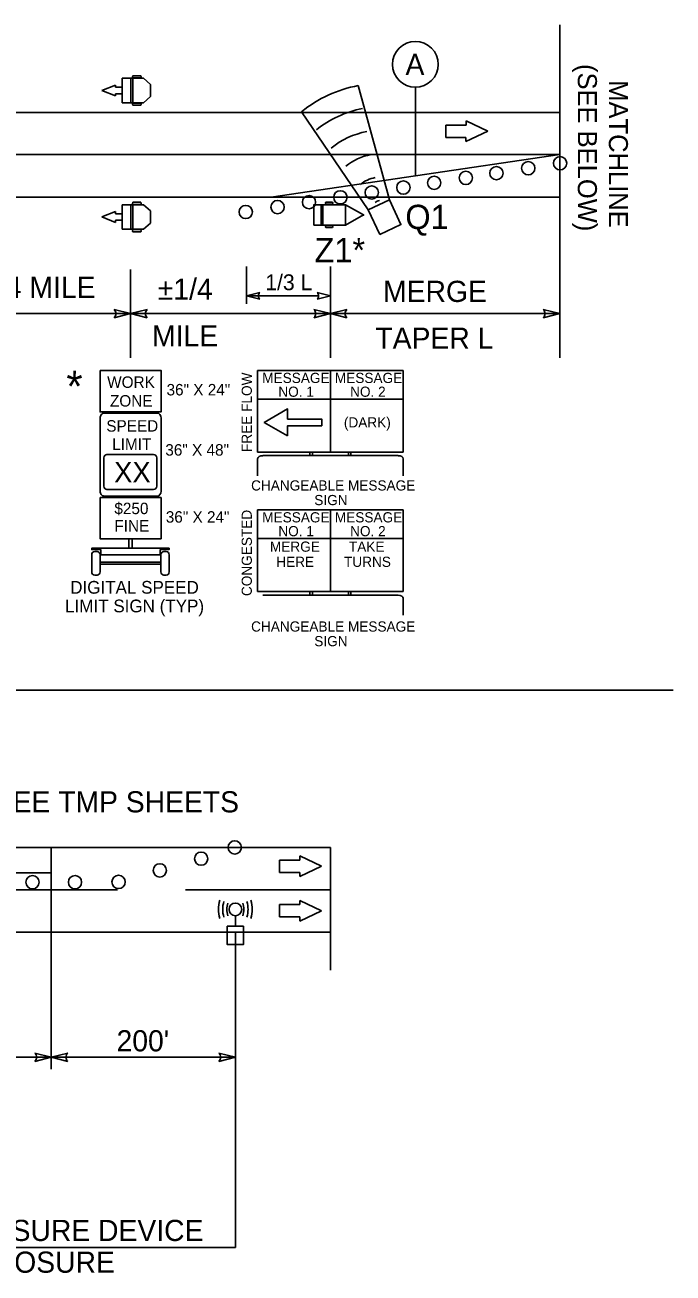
# Model space of a CAD drawing. Extents: x 1379436 to 1387057, y 792703 to 795604.
# Drawn here: x 1386649 to 1387057, y 794807 to 795592 of the extents above; entities that cross this region are included whole.
import ezdxf

# ---------------------------------------------------------------- set-up
doc = ezdxf.new("R2010")
doc.units = 0
for name, color, linetype in [('Black Area Fill Shapes', 7, 'Continuous'), ('Default', 7, 'Continuous'), ('DEV DIRECTION OF TRAFFIC FLOW ARROW CELL', 7, 'Continuous'), ('Gray Area Fill Shapes', 7, 'Continuous'), ('Old_Level_2', 7, 'Continuous'), ('Prop Mkg Skp Wht', 7, 'Continuous'), ('Prop Mkg Solid White Lane Line', 7, 'Continuous'), ('Prop Mkg Solid Yellow Edge Line', 7, 'Continuous'), ('Scratch_Level_0', 7, 'Continuous'), ('Text', 7, 'Continuous')]:
    doc.layers.add(name, color=color, linetype=linetype)

msp = doc.modelspace()

# ---------------------------------------------------------------- linework, layer by layer
at = {"layer": 'Black Area Fill Shapes'}
for points in [[(1386872.29, 795459.93), (1386865.13, 795475.48), (1386878.44, 795481.61), (1386885.6, 795466.07)], [(1386814.38, 795333.26), (1386799.7, 795341.73), (1386814.38, 795350.21), (1386814.38, 795343.86), (1386835.89, 795343.86), (1386835.89, 795339.6), (1386814.38, 795339.6)], [(1386714.52, 795262.58), (1386716.65, 795262.58), (1386716.65, 795268.56), (1386714.52, 795268.56)], [(1386696.46, 795252.5), (1386734.71, 795252.5), (1386734.71, 795253.77), (1386696.46, 795253.77)]]:
    msp.add_lwpolyline(points, close=True, dxfattribs=at)
for points in [[(1386734.7, 795262.58), (1386696.47, 795262.58), (1386691.29, 795262.57), (1386691.29, 795261.74), (1386696.85, 795261.74), (1386696.85, 795258.48), (1386734.3, 795258.51), (1386734.3, 795261.74)], [(1386696.47, 795262.58), (1386734.7, 795262.58), (1386739.88, 795262.57), (1386739.88, 795261.74), (1386734.3, 795261.75), (1386734.29, 795258.46), (1386696.85, 795258.48), (1386696.85, 795261.74)], [(1386691.21, 795247.81), (1386691.21, 795258.46)], [(1386693.12, 795260.54), (1386694.55, 795260.54)], [(1386696.46, 795258.46), (1386696.46, 795247.81)], [(1386734.71, 795247.81), (1386734.71, 795258.46)], [(1386736.62, 795260.54), (1386738.05, 795260.54)], [(1386739.96, 795258.46), (1386739.96, 795247.81)], [(1386694.55, 795245.74), (1386693.12, 795245.74)], [(1386738.05, 795245.74), (1386736.62, 795245.74)]]:
    msp.add_lwpolyline(points, dxfattribs=at)
for centre in [(1386985.71, 795504.66), (1386926.49, 795495.49), (1386945.7, 795498.46), (1386965.73, 795501.56), (1386867.28, 795486.31), (1386887.19, 795489.4), (1386906.57, 795492.4), (1386827.86, 795480.21), (1386847.57, 795483.26), (1386788.06, 795474.04), (1386808.08, 795477.14), (1386781.14, 795074.47), (1386760.03, 795067.39), (1386734.07, 795060.04), (1386653.98, 795052.57), (1386680.72, 795052.58), (1386708.13, 795052.74)]:
    msp.add_circle(centre, 4.18, dxfattribs=at)
for centre, major_axis, start_param, end_param in [((1386693.12, 795258.46), (0, 2.08), 0, 1.570796), ((1386694.55, 795258.46), (0, 2.08), 4.712389, 6.283185), ((1386736.62, 795258.46), (0, -2.08), 3.141593, 4.712389), ((1386738.05, 795258.46), (0, 2.08), 4.712389, 6.283185), ((1386693.12, 795247.81), (0, -2.08), 4.712389, 6.283185), ((1386694.55, 795247.81), (0, -2.08), 0, 1.570796), ((1386736.62, 795247.81), (0, -2.08), 4.712389, 6.283185), ((1386738.05, 795247.81), (0, 2.08), 3.141593, 4.712389)]:
    msp.add_ellipse(centre, major_axis=major_axis, ratio=0.917264, start_param=start_param, end_param=end_param, dxfattribs=at)
at = {"layer": 'Default'}
for p, q in [((1386985.54, 795428.56), (1386985.54, 795591.65)), ((1386894.75, 795496.78), (1386894.75, 795552.5)), ((1386715.67, 795437.87), (1386715.67, 795382.35)), ((1386788.53, 795439.68), (1386788.53, 795416.27)), ((1386841.32, 795439.68), (1386841.32, 795382.35)), ((1386985.54, 795439.68), (1386985.54, 795382.35)), ((1386788.53, 795421.29), (1386833.85, 795421.29)), ((1386985.54, 795410.11), (1385695.67, 795410.11)), ((1384806.76, 795173.42), (1387056.77, 795173.42))]:
    msp.add_line(p, q, dxfattribs=at)
for points in [[(1386696.55, 795298.44), (1386696.55, 795344.47)], [(1386698.78, 795347.51), (1386732.56, 795347.51)], [(1386734.79, 795344.47), (1386734.79, 795298.44)], [(1386732.56, 795295.4), (1386698.78, 795295.4)]]:
    msp.add_lwpolyline(points, dxfattribs=at)
msp.add_circle((1386894.75, 795566.87), 14.37, dxfattribs=at)
for centre, major_axis, start_param, end_param in [((1386698.78, 795344.47), (0, 3.04), 6.282958, 7.853982), ((1386732.56, 795344.47), (0, 3.04), 4.712389, 6.283185), ((1386698.78, 795298.44), (0, 3.04), 1.570796, 3.141593), ((1386732.56, 795298.44), (0, -3.04), 0, 1.570796)]:
    msp.add_ellipse(centre, major_axis=major_axis, ratio=0.733811, start_param=start_param, end_param=end_param, dxfattribs=at)
at = {"layer": 'DEV DIRECTION OF TRAFFIC FLOW ARROW CELL'}
for p, q in [((1386940.34, 795524.82), (1386926.58, 795531.31)), ((1386926.58, 795531.31), (1386926.58, 795528.69)), ((1386926.58, 795528.69), (1386913.8, 795528.7)), ((1386913.8, 795528.7), (1386913.8, 795520.98)), ((1386926.57, 795518.35), (1386940.34, 795524.82)), ((1386913.8, 795520.98), (1386926.57, 795520.98)), ((1386926.57, 795520.98), (1386926.57, 795518.35)), ((1386822.01, 795066.46), (1386809.24, 795066.47)), ((1386809.24, 795066.47), (1386809.24, 795058.76)), ((1386822.02, 795069.08), (1386822.01, 795066.46)), ((1386835.77, 795062.59), (1386822.02, 795069.08)), ((1386809.24, 795058.76), (1386822.01, 795058.75)), ((1386822.01, 795056.13), (1386835.77, 795062.59)), ((1386822.01, 795058.75), (1386822.01, 795056.13)), ((1386822.01, 795038.52), (1386809.24, 795038.53)), ((1386809.24, 795038.53), (1386809.24, 795030.82)), ((1386822.02, 795041.14), (1386822.01, 795038.52)), ((1386835.77, 795034.66), (1386822.02, 795041.14)), ((1386809.24, 795030.82), (1386822.01, 795030.81)), ((1386822.01, 795028.19), (1386835.77, 795034.66)), ((1386822.01, 795030.81), (1386822.01, 795028.19))]:
    msp.add_line(p, q, dxfattribs=at)
at = {"layer": 'Gray Area Fill Shapes'}
for p, q in [((1386698.81, 795319.44), (1386698.81, 795301.68)), ((1386730.09, 795321.6), (1386700.79, 795321.6)), ((1386732.07, 795301.68), (1386732.07, 795319.44)), ((1386700.79, 795299.52), (1386730.09, 795299.52))]:
    msp.add_line(p, q, dxfattribs=at)
msp.add_lwpolyline([(1386573.89, 795074.47), (1386665.77, 795074.47), (1386665.77, 795058.54), (1386573.89, 795058.54)], close=True, dxfattribs=at)
for centre, major_axis, start_param, end_param in [((1386700.79, 795319.44), (0, 2.16), 0, 1.570796), ((1386730.09, 795319.44), (0, 2.16), 4.712389, 6.283185), ((1386700.79, 795301.68), (0, -2.16), 4.712389, 6.283185), ((1386730.09, 795301.68), (0, -2.16), 0, 1.570796)]:
    msp.add_ellipse(centre, major_axis=major_axis, ratio=0.917264, start_param=start_param, end_param=end_param, dxfattribs=at)
at = {"layer": 'Old_Level_2'}
for points in [[(1386696.53, 795374.43), (1386734.82, 795374.43), (1386734.82, 795348.37), (1386696.53, 795348.37)], [(1386696.5, 795294.5), (1386734.79, 795294.5), (1386734.79, 795268.56), (1386696.5, 795268.56)]]:
    msp.add_lwpolyline(points, close=True, dxfattribs=at)
at = {"layer": 'Prop Mkg Skp Wht'}
for p, q in [((1385896.18, 795510.08), (1386985.54, 795510.09)), ((1386750.26, 795047.86), (1386841.41, 795047.86))]:
    msp.add_line(p, q, dxfattribs=at)
at = {"layer": 'Prop Mkg Solid White Lane Line'}
for p, q in [((1386706.24, 795553.83), (1386697.54, 795550.45)), ((1386706.24, 795552.46), (1386706.24, 795553.83)), ((1386710.27, 795558.15), (1386723.7, 795558.15)), ((1386710.27, 795558.15), (1386710.27, 795542.73)), ((1386715.85, 795558.15), (1386710.27, 795558.15)), ((1386710.27, 795558.15), (1386710.27, 795542.73)), ((1386715.85, 795542.73), (1386715.85, 795558.15)), ((1386717.13, 795542.72), (1386717.13, 795558.15)), ((1386717.14, 795559.73), (1386722.07, 795559.73)), ((1386717.14, 795558.33), (1386722.07, 795558.33)), ((1386728.18, 795554.3), (1386723.7, 795558.15)), ((1386728.18, 795546.59), (1386728.18, 795554.3)), ((1386728.18, 795554.3), (1386728.18, 795550.44)), ((1386697.54, 795550.45), (1386706.23, 795547.06)), ((1386706.23, 795547.06), (1386706.23, 795548.43)), ((1386706.23, 795548.43), (1386710.27, 795548.43)), ((1386710.27, 795552.46), (1386706.24, 795552.46)), ((1386710.27, 795548.43), (1386710.27, 795552.46)), ((1386723.7, 795542.73), (1386728.18, 795546.59)), ((1386728.18, 795550.44), (1386728.18, 795546.59)), ((1386710.27, 795542.73), (1386723.7, 795542.73)), ((1386710.27, 795542.73), (1386715.85, 795542.73)), ((1386717.15, 795542.54), (1386722.08, 795542.54)), ((1386722.08, 795541.15), (1386717.15, 795541.15)), ((1386985.54, 795510.09), (1386803.97, 795483.46)), ((1385896.18, 795483.46), (1386985.54, 795483.46)), ((1386710.27, 795478.59), (1386723.7, 795478.59)), ((1386710.27, 795478.59), (1386710.27, 795463.17)), ((1386715.85, 795478.59), (1386710.27, 795478.59)), ((1386710.27, 795478.59), (1386710.27, 795463.17)), ((1386715.85, 795463.17), (1386715.85, 795478.59)), ((1386717.13, 795463.16), (1386717.13, 795478.59)), ((1386717.14, 795480.17), (1386722.07, 795480.17)), ((1386717.14, 795478.77), (1386722.07, 795478.77)), ((1386728.18, 795474.73), (1386723.7, 795478.59)), ((1386728.18, 795467.02), (1386728.18, 795474.73)), ((1386728.18, 795474.73), (1386728.18, 795470.88)), ((1386830.89, 795478.65), (1386830.89, 795465.72)), ((1386830.89, 795478.64), (1386850.89, 795478.64)), ((1386830.89, 795465.71), (1386830.89, 795478.64)), ((1386835.56, 795465.71), (1386835.56, 795478.64)), ((1386836.64, 795465.71), (1386836.64, 795478.64)), ((1386838.44, 795480.27), (1386842.57, 795480.27)), ((1386838.44, 795479.05), (1386842.57, 795479.05)), ((1386850.89, 795465.72), (1386850.89, 795478.64)), ((1386850.89, 795478.64), (1386862.07, 795472.18)), ((1386706.24, 795474.27), (1386697.54, 795470.89)), ((1386697.54, 795470.89), (1386706.23, 795467.49)), ((1386706.23, 795467.49), (1386706.23, 795468.87)), ((1386706.23, 795468.87), (1386710.27, 795468.86)), ((1386706.24, 795472.9), (1386706.24, 795474.27)), ((1386710.27, 795472.9), (1386706.24, 795472.9)), ((1386710.27, 795468.86), (1386710.27, 795472.9)), ((1386723.7, 795463.17), (1386728.18, 795467.02)), ((1386728.18, 795470.88), (1386728.18, 795467.02)), ((1386850.89, 795465.72), (1386862.07, 795472.18)), ((1386710.27, 795463.17), (1386723.7, 795463.17)), ((1386710.27, 795463.17), (1386715.85, 795463.17)), ((1386717.15, 795462.98), (1386722.08, 795462.98)), ((1386722.08, 795461.58), (1386717.15, 795461.58)), ((1386830.89, 795465.72), (1386850.89, 795465.72)), ((1386838.44, 795465.46), (1386842.57, 795465.46)), ((1386838.44, 795464.29), (1386842.57, 795464.29)), ((1386795.56, 795374.43), (1386887.07, 795374.43)), ((1386795.56, 795322.95), (1386795.56, 795374.43)), ((1386841.32, 795322.95), (1386841.32, 795374.43)), ((1386841.32, 795322.95), (1386841.32, 795374.43)), ((1386887.07, 795322.95), (1386887.07, 795374.43)), ((1386795.56, 795356.32), (1386841.32, 795356.32)), ((1386887.07, 795356.32), (1386841.32, 795356.32)), ((1386887.07, 795322.95), (1386795.56, 795322.95)), ((1386795.56, 795318.82), (1386795.56, 795308.2)), ((1386798.77, 795320.82), (1386883.85, 795320.82)), ((1386828.45, 795322.95), (1386828.45, 795320.82)), ((1386830.03, 795322.95), (1386830.03, 795320.82)), ((1386852.6, 795322.95), (1386852.6, 795320.82)), ((1386854.18, 795322.95), (1386854.18, 795320.82)), ((1386887.09, 795318.84), (1386887.09, 795308.22)), ((1386795.56, 795286.76), (1386887.07, 795286.76)), ((1386795.56, 795235.29), (1386795.56, 795286.76)), ((1386841.32, 795235.29), (1386841.32, 795286.76)), ((1386841.32, 795235.29), (1386841.32, 795286.76)), ((1386887.07, 795235.29), (1386887.07, 795286.76)), ((1386795.56, 795268.65), (1386841.32, 795268.65)), ((1386887.07, 795268.65), (1386841.32, 795268.65)), ((1386887.07, 795235.29), (1386795.56, 795235.29)), ((1386798.77, 795233.16), (1386883.85, 795233.16)), ((1386828.45, 795235.29), (1386828.45, 795233.16)), ((1386830.03, 795235.29), (1386830.03, 795233.16)), ((1386852.6, 795235.29), (1386852.6, 795233.16)), ((1386854.18, 795235.29), (1386854.18, 795233.16)), ((1386887.09, 795231.17), (1386887.09, 795220.55)), ((1386167.25, 795021.25), (1386841.41, 795021.25))]:
    msp.add_line(p, q, dxfattribs=at)
for points in [[(1386796.95, 795419.19), (1386788.53, 795421.29), (1386796.95, 795423.4)], [(1386796.95, 795419.19), (1386788.53, 795421.29), (1386796.95, 795423.4)], [(1386832.9, 795419.19), (1386841.32, 795421.29), (1386832.9, 795423.4)], [(1386832.9, 795419.19), (1386841.32, 795421.29), (1386832.9, 795423.4)], [(1386705.28, 795407.51), (1386715.67, 795410.11), (1386705.28, 795412.71)], [(1386705.28, 795407.51), (1386715.67, 795410.11), (1386705.28, 795412.71)], [(1386726.07, 795407.51), (1386715.67, 795410.11), (1386726.07, 795412.71)], [(1386726.07, 795407.51), (1386715.67, 795410.11), (1386726.07, 795412.71)], [(1386830.92, 795407.51), (1386841.32, 795410.11), (1386830.92, 795412.71)], [(1386830.92, 795407.51), (1386841.32, 795410.11), (1386830.92, 795412.71)], [(1386851.71, 795407.51), (1386841.32, 795410.11), (1386851.71, 795412.71)], [(1386851.71, 795407.51), (1386841.32, 795410.11), (1386851.71, 795412.71)], [(1386975.14, 795407.51), (1386985.54, 795410.11), (1386975.14, 795412.71)], [(1386975.14, 795407.51), (1386985.54, 795410.11), (1386975.14, 795412.71)], [(1386655.38, 794939.93), (1386665.77, 794942.53), (1386655.38, 794945.13)], [(1386655.38, 794939.93), (1386665.77, 794942.53), (1386655.38, 794945.13)], [(1386676.16, 794939.93), (1386665.77, 794942.53), (1386676.16, 794945.13)], [(1386676.16, 794939.93), (1386665.77, 794942.53), (1386676.16, 794945.13)], [(1386771.16, 794939.94), (1386781.55, 794942.54), (1386771.16, 794945.13)], [(1386771.16, 794939.94), (1386781.55, 794942.54), (1386771.16, 794945.13)]]:
    msp.add_lwpolyline(points, dxfattribs=at)
msp.add_circle((1386862.19, 795472.17), 0.114, dxfattribs=at)
for centre, radius, start, end in [((1386718.04, 795559.03), 1.14, 142.08835, 217.91165), ((1386721.17, 795559.03), 1.14, 322.08835, 37.91165), ((1386718.05, 795541.84), 1.14, 142.08835, 217.91165), ((1386721.18, 795541.84), 1.14, 322.08835, 37.91165), ((1386718.04, 795479.47), 1.14, 142.08835, 217.91165), ((1386721.17, 795479.47), 1.14, 322.08835, 37.91165), ((1386839.19, 795479.63), 0.954, 142.08835, 217.91165), ((1386841.82, 795479.63), 0.954, 322.08835, 37.91165), ((1386718.05, 795462.28), 1.14, 142.08835, 217.91165), ((1386721.18, 795462.28), 1.14, 322.08835, 37.91165), ((1386839.19, 795464.88), 0.954, 142.08835, 217.91165), ((1386841.82, 795464.88), 0.954, 322.08835, 37.91165), ((1386798.8, 795421.29), 2.8, 131.32643, 228.67356), ((1386798.8, 795421.29), 2.8, 131.32643, 228.67356), ((1386831.05, 795421.29), 2.8, 311.32644, 48.67357), ((1386831.05, 795421.29), 2.8, 311.32644, 48.67357), ((1386702.99, 795410.11), 3.46, 311.32644, 48.67357), ((1386702.99, 795410.11), 3.46, 311.32644, 48.67357), ((1386728.35, 795410.11), 3.46, 131.32643, 228.67356), ((1386728.35, 795410.11), 3.46, 131.32643, 228.67356), ((1386828.64, 795410.11), 3.46, 311.32644, 48.67357), ((1386828.64, 795410.11), 3.46, 311.32644, 48.67357), ((1386854, 795410.11), 3.46, 131.32643, 228.67356), ((1386854, 795410.11), 3.46, 131.32643, 228.67356), ((1386972.86, 795410.11), 3.46, 311.32644, 48.67357), ((1386972.86, 795410.11), 3.46, 311.32644, 48.67357), ((1386653.09, 794942.53), 3.46, 311.32644, 48.67357), ((1386653.09, 794942.53), 3.46, 311.32644, 48.67357), ((1386678.45, 794942.53), 3.46, 131.32643, 228.67356), ((1386678.45, 794942.53), 3.46, 131.32643, 228.67356), ((1386768.88, 794942.54), 3.46, 311.32644, 48.67357), ((1386768.88, 794942.54), 3.46, 311.32644, 48.67357)]:
    msp.add_arc(centre, radius, start, end, dxfattribs=at)
for centre, major_axis, start_param, end_param in [((1386798.78, 795318.84), (-3.24, 0), 4.712389, 6.283185), ((1386883.85, 795318.84), (3.24, 0), 0, 1.570796), ((1386883.85, 795231.17), (3.24, 0), 0, 1.570796)]:
    msp.add_ellipse(centre, major_axis=major_axis, ratio=0.606795, start_param=start_param, end_param=end_param, dxfattribs=at)
at = {"layer": 'Prop Mkg Solid Yellow Edge Line'}
for p, q in [((1385896.18, 795536.7), (1386985.54, 795536.7)), ((1386167.25, 795074.47), (1386841.41, 795074.47)), ((1386387.94, 795047.86), (1386707.5, 795047.86))]:
    msp.add_line(p, q, dxfattribs=at)
at = {"layer": 'Scratch_Level_0'}
msp.add_line((1386841.41, 795074.47), (1386841.41, 794997.37), dxfattribs=at)
at = {"layer": 'Text'}
for p, q in [((1386878.44, 795481.61), (1386858.8, 795553.5)), ((1386865.13, 795475.48), (1386823.24, 795537.11)), ((1386723.28, 795074.47), (1386799.87, 795074.47)), ((1386665.77, 795058.54), (1386665.77, 794935.06)), ((1386781.55, 795024.88), (1386781.55, 795031.53)), ((1386781.55, 795021.25), (1386781.55, 794822.93)), ((1386573.89, 794942.53), (1386665.77, 794942.53)), ((1386665.79, 794942.53), (1386781.55, 794942.54)), ((1386781.55, 794822.93), (1386435.35, 794822.93))]:
    msp.add_line(p, q, dxfattribs=at)
msp.add_lwpolyline([(1386776.48, 795024.88), (1386786.66, 795024.88), (1386786.66, 795013.38), (1386776.48, 795013.38)], close=True, dxfattribs=at)
msp.add_circle((1386781.55, 795035.52), 3.99, dxfattribs=at)
for centre, radius, start, end in [((1386873.24, 795475.38), 79.44, 100.47314, 129.0092), ((1386873.24, 795475.38), 64.74, 100.47314, 129.0092), ((1386873.24, 795475.38), 50.04, 100.47314, 129.0092), ((1386873.24, 795475.38), 35.34, 100.47314, 129.0092), ((1386873.24, 795475.38), 20.63, 100.47314, 129.0092), ((1386873.24, 795475.38), 5.93, 100.47314, 129.0092), ((1386788.53, 795035.52), 17.62, 161.06571, 198.93429), ((1386788.53, 795035.52), 14.96, 161.06571, 198.93429), ((1386788.53, 795035.52), 12.3, 161.06571, 198.93429), ((1386774.58, 795035.52), 12.3, 341.06571, 18.93429), ((1386774.58, 795035.52), 14.96, 341.06571, 18.93429), ((1386774.58, 795035.52), 17.62, 341.06571, 18.93429)]:
    msp.add_arc(centre, radius, start, end, dxfattribs=at)

# ---------------------------------------------------------------- texts
at = {"layer": 'Default'}
for s, p in [('(SEE BELOW)', (1386996.9, 795567.09)), ('MATCHLINE', (1387016.4, 795556.87))]:
    msp.add_text(s, height=12, rotation=270, dxfattribs=at).set_placement(p)
for s, height, p in [('*', 19.68, (1386675.28, 795354.59)), ('36" X 24"', 7.203, (1386738.27, 795358.69)), ('36" X 48"', 7.203, (1386737.5, 795320.84)), ('36" X 24"', 7.203, (1386737.8, 795278.69))]:
    msp.add_text(s, height=height, dxfattribs=at).set_placement(p)
at = {"layer": 'Prop Mkg Solid White Lane Line'}
for s, p in [('FREE FLOW', (1386791.91, 795323.13)), ('CONGESTED', (1386791.91, 795232.53))]:
    msp.add_text(s, height=6.403, rotation=90, dxfattribs=at).set_placement(p)
for s, height, p in [('MESSAGE', 6.403, (1386798.45, 795366.5)), ('MESSAGE', 6.403, (1386844.12, 795366.5)), ('NO. 1', 6.403, (1386808.57, 795357.83)), ('NO. 2', 6.403, (1386853.7, 795357.83)), ('(DARK)', 6.403, (1386849.79, 795338.53)), ('CHANGEABLE MESSAGE', 6.4025, (1386791.45, 795298.89)), ('SIGN', 6.403, (1386831.18, 795289.7)), ('MESSAGE', 6.403, (1386798.45, 795278.84)), ('MESSAGE', 6.403, (1386844.12, 795278.84)), ('NO. 1', 6.403, (1386808.57, 795270.16)), ('NO. 2', 6.403, (1386853.7, 795270.16)), ('MERGE', 6.403, (1386803.29, 795260.41)), ('TAKE', 6.403, (1386852.96, 795260.41)), ('HERE', 6.403, (1386807.25, 795250.87)), ('TURNS', 6.403, (1386849.86, 795250.87)), ('CHANGEABLE MESSAGE', 6.4025, (1386791.45, 795210.18)), ('SIGN', 6.403, (1386831.18, 795200.99))]:
    msp.add_text(s, height=height, dxfattribs=at).set_placement(p)
at = {"layer": 'Text'}
for s, height, p in [('A', 13.31, (1386888.54, 795560.21)), ('Q1', 15.29, (1386888.42, 795463.29)), ('Z1*', 15.29, (1386831.31, 795442.42)), ('1/3 L', 9.942, (1386800.37, 795424.87)), ('±1/4 MILE', 13.31, (1386612.6, 795420.03)), ('±1/4', 13.31, (1386732.78, 795418.88)), ('MERGE ', 13.31, (1386874.43, 795417.48)), ('MILE', 13.31, (1386729.15, 795389.46)), ('TAPER L', 13.31, (1386869.6, 795388.07)), ('WORK', 7.203, (1386700.94, 795363.44)), ('ZONE', 7.203, (1386702.71, 795351.68)), ('XX', 12.879, (1386705.32, 795304.01)), ('$250', 7.203, (1386705.47, 795284.04)), ('FINE', 7.203, (1386705.47, 795273.08)), ('DIGITAL SPEED', 8.0031, (1386677.69, 795234.02)), ('LIMIT SIGN (TYP)', 8.0031, (1386674.48, 795222.29)), ('SEE TMP SHEETS', 13.3038, (1386629.63, 795096.48)), ("200'", 13.304, (1386706.84, 794946.22)), ('CONNECTED LANE CLOSURE DEVICE', 13.3038, (1386435.24, 794826.97)), ('END OF LANE CLOSURE', 13.3038, (1386496.19, 794807.01))]:
    msp.add_text(s, height=height, dxfattribs=at).set_placement(p)
for s, p in [('SPEED', (1386700.39, 795335.92)), ('LIMIT', (1386704.09, 795324.42))]:
    msp.add_text(s, height=7.203, rotation=360, dxfattribs=at).set_placement(p)

doc.saveas('drawing.dxf')
